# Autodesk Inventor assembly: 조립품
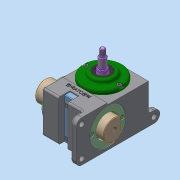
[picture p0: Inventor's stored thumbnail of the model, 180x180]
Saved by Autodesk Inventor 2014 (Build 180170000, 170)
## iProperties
Created: 2023-09
Part Number: 조립품
Document SubType Name: Assembly
Designer: dg
Author: dg
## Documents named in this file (11)
- C:\Users\dg\Desktop\730906V1006\조립품.iam
- C:\Users\dg\Desktop\730906V1006\본체.ipt
- C:\Users\dg\Desktop\730906V1006\가이드 부시.ipt
- C:\Users\dg\Desktop\730906V1006\래크.ipt
- C:\Users\dg\Desktop\730906V1006\베어링 6003.ipt
- C:\Users\dg\Desktop\730906V1006\볼트 M4.ipt
- C:\Users\dg\Desktop\730906V1006\부시 커버.ipt
- C:\Users\dg\Desktop\730906V1006\스톱퍼.ipt
- C:\Users\dg\Desktop\730906V1006\앞커버.ipt
- C:\Users\dg\Desktop\730906V1006\오일 실 17 30 5.ipt
- C:\Users\dg\Desktop\730906V1006\피니언.ipt
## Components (3 placed, 2 different names)
1. 가이드 부시:1
2. 피니언:1
3. 가이드 부시:2
